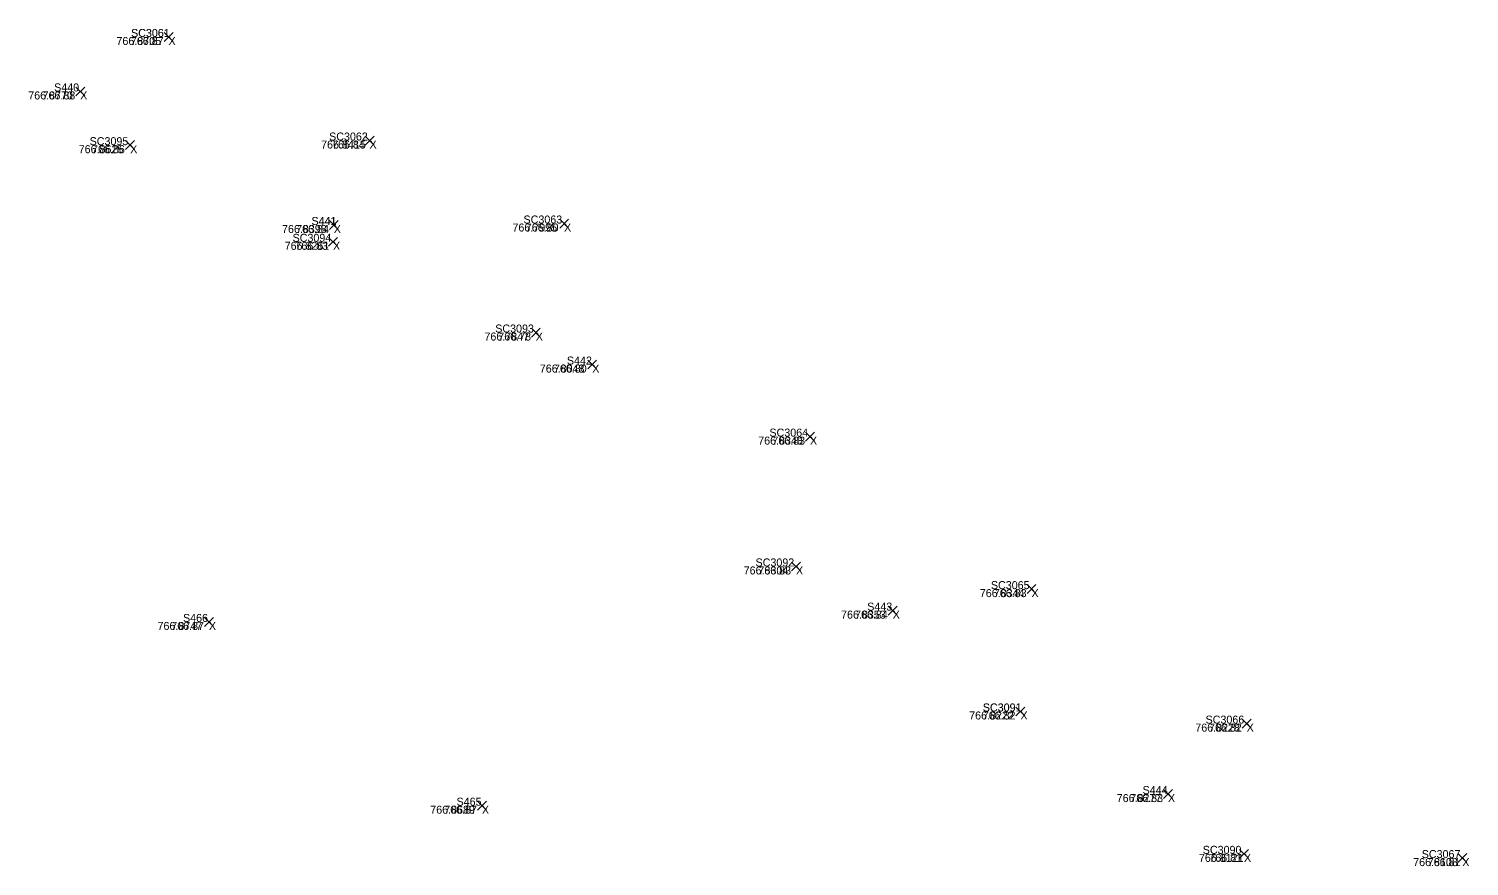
# Model space of a CAD drawing. Extents: x 1845019 to 1877956, y 680444 to 701081.
# Drawn here: x 1857801.14 to 1857811.93, y 694200.78 to 694207.06 of the extents above; entities that cross this region are included whole.
import ezdxf

# ---------------------------------------------------------------- set-up
doc = ezdxf.new("R2010")
doc.units = 0
for name, color, linetype in [('SV_X_Random_Point', 7, 'Continuous'), ('SV_X_Text_Comment', 7, 'Continuous'), ('SV_X_Text_Elevation', 7, 'Continuous'), ('SV_X_Text_Name', 7, 'Continuous')]:
    doc.layers.add(name, color=color, linetype=linetype)

msp = doc.modelspace()

# ---------------------------------------------------------------- linework, layer by layer
at = {"layer": 'SV_X_Random_Point'}
for p, q in [((1857802.152, 694206.966), (1857802.219, 694207.033)), ((1857802.152, 694207.033), (1857802.219, 694206.966)), ((1857802.152, 694206.966), (1857802.219, 694207.033)), ((1857802.152, 694207.033), (1857802.219, 694206.966)), ((1857801.49, 694206.558), (1857801.557, 694206.624)), ((1857801.49, 694206.624), (1857801.557, 694206.558)), ((1857801.49, 694206.558), (1857801.557, 694206.624)), ((1857801.49, 694206.624), (1857801.557, 694206.558)), ((1857801.864, 694206.155), (1857801.931, 694206.222)), ((1857801.864, 694206.222), (1857801.931, 694206.155)), ((1857801.864, 694206.155), (1857801.931, 694206.222)), ((1857801.864, 694206.222), (1857801.931, 694206.155)), ((1857803.659, 694206.189), (1857803.726, 694206.256)), ((1857803.659, 694206.256), (1857803.726, 694206.189)), ((1857803.659, 694206.189), (1857803.726, 694206.256)), ((1857803.659, 694206.256), (1857803.726, 694206.189)), ((1857803.391, 694205.556), (1857803.457, 694205.623)), ((1857803.391, 694205.623), (1857803.457, 694205.556)), ((1857803.391, 694205.556), (1857803.457, 694205.623)), ((1857803.391, 694205.623), (1857803.457, 694205.556)), ((1857805.117, 694205.567), (1857805.183, 694205.634)), ((1857805.117, 694205.634), (1857805.183, 694205.567)), ((1857805.117, 694205.567), (1857805.183, 694205.634)), ((1857805.117, 694205.634), (1857805.183, 694205.567)), ((1857803.385, 694205.431), (1857803.452, 694205.497)), ((1857803.385, 694205.497), (1857803.452, 694205.431)), ((1857803.385, 694205.431), (1857803.452, 694205.497)), ((1857803.385, 694205.497), (1857803.452, 694205.431)), ((1857804.905, 694204.75), (1857804.972, 694204.817)), ((1857804.905, 694204.817), (1857804.972, 694204.75)), ((1857804.905, 694204.75), (1857804.972, 694204.817)), ((1857804.905, 694204.817), (1857804.972, 694204.75)), ((1857805.328, 694204.511), (1857805.394, 694204.578)), ((1857805.328, 694204.578), (1857805.394, 694204.511)), ((1857805.328, 694204.511), (1857805.394, 694204.578)), ((1857805.328, 694204.578), (1857805.394, 694204.511)), ((1857806.959, 694203.971), (1857807.026, 694204.037)), ((1857806.959, 694204.037), (1857807.026, 694203.971)), ((1857806.959, 694203.971), (1857807.026, 694204.037)), ((1857806.959, 694204.037), (1857807.026, 694203.971)), ((1857806.855, 694202.997), (1857806.922, 694203.064)), ((1857806.855, 694203.064), (1857806.922, 694202.997)), ((1857806.855, 694202.997), (1857806.922, 694203.064)), ((1857806.855, 694203.064), (1857806.922, 694202.997)), ((1857808.62, 694202.828), (1857808.686, 694202.895)), ((1857808.62, 694202.895), (1857808.686, 694202.828)), ((1857808.62, 694202.828), (1857808.686, 694202.895)), ((1857808.62, 694202.895), (1857808.686, 694202.828)), ((1857807.579, 694202.666), (1857807.646, 694202.733)), ((1857807.579, 694202.733), (1857807.646, 694202.666)), ((1857807.579, 694202.666), (1857807.646, 694202.733)), ((1857807.579, 694202.733), (1857807.646, 694202.666)), ((1857802.455, 694202.582), (1857802.522, 694202.649)), ((1857802.455, 694202.649), (1857802.522, 694202.582)), ((1857802.455, 694202.582), (1857802.522, 694202.649)), ((1857802.455, 694202.649), (1857802.522, 694202.582)), ((1857808.536, 694201.911), (1857808.603, 694201.977)), ((1857808.536, 694201.977), (1857808.603, 694201.911)), ((1857808.536, 694201.911), (1857808.603, 694201.977)), ((1857808.536, 694201.977), (1857808.603, 694201.911)), ((1857810.232, 694201.82), (1857810.299, 694201.886)), ((1857810.232, 694201.886), (1857810.299, 694201.82)), ((1857810.232, 694201.82), (1857810.299, 694201.886)), ((1857810.232, 694201.886), (1857810.299, 694201.82)), ((1857809.643, 694201.291), (1857809.709, 694201.358)), ((1857809.643, 694201.358), (1857809.709, 694201.291)), ((1857809.643, 694201.291), (1857809.709, 694201.358)), ((1857809.643, 694201.358), (1857809.709, 694201.291)), ((1857804.501, 694201.205), (1857804.568, 694201.272)), ((1857804.501, 694201.272), (1857804.568, 694201.205)), ((1857804.501, 694201.205), (1857804.568, 694201.272)), ((1857804.501, 694201.272), (1857804.568, 694201.205)), ((1857810.212, 694200.844), (1857810.279, 694200.91)), ((1857810.212, 694200.91), (1857810.279, 694200.844)), ((1857810.212, 694200.844), (1857810.279, 694200.91)), ((1857810.212, 694200.91), (1857810.279, 694200.844)), ((1857811.849, 694200.812), (1857811.915, 694200.879)), ((1857811.849, 694200.879), (1857811.915, 694200.812)), ((1857811.849, 694200.812), (1857811.915, 694200.879)), ((1857811.849, 694200.879), (1857811.915, 694200.812))]:
    msp.add_line(p, q, dxfattribs=at)

# ---------------------------------------------------------------- texts
at = {"layer": 'SV_X_Text_Comment'}
for p in [(1857802.185, 694206.939), (1857801.523, 694206.531), (1857801.898, 694206.128), (1857803.692, 694206.163), (1857803.424, 694205.53), (1857805.15, 694205.541), (1857803.418, 694205.404), (1857804.938, 694204.724), (1857805.361, 694204.484), (1857806.993, 694203.944), (1857806.888, 694202.971), (1857808.653, 694202.801), (1857807.613, 694202.64), (1857802.488, 694202.555), (1857808.57, 694201.884), (1857810.266, 694201.793), (1857809.676, 694201.265), (1857804.534, 694201.178), (1857810.246, 694200.817), (1857811.882, 694200.785)]:
    msp.add_text('X', height=0.06, dxfattribs=at).set_placement(p)
at = {"layer": 'SV_X_Text_Elevation'}
for s, p in [('766.8705', (1857801.795, 694206.939)), ('766.87', (1857801.903, 694206.939)), ('766.8770', (1857801.134, 694206.531)), ('766.88', (1857801.241, 694206.531)), ('766.8625', (1857801.512, 694206.128)), ('766.86', (1857801.612, 694206.128)), ('766.8415', (1857803.329, 694206.163)), ('766.84', (1857803.411, 694206.163)), ('766.8398', (1857803.036, 694205.53)), ('766.84', (1857803.142, 694205.53)), ('766.7995', (1857804.763, 694205.541)), ('766.80', (1857804.863, 694205.541)), ('766.8261', (1857803.056, 694205.404)), ('766.83', (1857803.136, 694205.404)), ('766.7847', (1857804.553, 694204.724)), ('766.78', (1857804.657, 694204.724)), ('766.8048', (1857804.968, 694204.484)), ('766.80', (1857805.074, 694204.484)), ('766.8348', (1857806.605, 694203.944)), ('766.83', (1857806.711, 694203.944)), ('766.8304', (1857806.496, 694202.971)), ('766.83', (1857806.606, 694202.971)), ('766.8344', (1857808.266, 694202.801)), ('766.83', (1857808.371, 694202.801)), ('766.8353', (1857807.226, 694202.64)), ('766.84', (1857807.331, 694202.64)), ('766.8747', (1857802.103, 694202.555)), ('766.87', (1857802.206, 694202.555)), ('766.8222', (1857808.186, 694201.884)), ('766.82', (1857808.288, 694201.884)), ('766.8228', (1857809.881, 694201.793)), ('766.82', (1857809.984, 694201.793)), ('766.8277', (1857809.292, 694201.265)), ('766.83', (1857809.394, 694201.265)), ('766.8689', (1857804.147, 694201.178)), ('766.87', (1857804.252, 694201.178)), ('766.8121', (1857809.908, 694200.817)), ('766.81', (1857809.986, 694200.817)), ('766.8108', (1857811.514, 694200.785)), ('766.81', (1857811.623, 694200.785))]:
    msp.add_text(s, height=0.06, dxfattribs=at).set_placement(p)
at = {"layer": 'SV_X_Text_Name'}
for s, p in [('SC3061', (1857801.904, 694206.999)), ('SC3061', (1857801.905, 694206.999)), ('S440', (1857801.328, 694206.591)), ('S440', (1857801.328, 694206.591)), ('SC3062', (1857803.389, 694206.223)), ('SC3062', (1857803.389, 694206.223)), ('SC3095', (1857801.594, 694206.188)), ('SC3095', (1857801.594, 694206.188)), ('S441', (1857803.256, 694205.59)), ('S441', (1857803.257, 694205.59)), ('SC3063', (1857804.846, 694205.601)), ('SC3063', (1857804.846, 694205.601)), ('SC3094', (1857803.115, 694205.464)), ('SC3094', (1857803.115, 694205.464)), ('SC3093', (1857804.634, 694204.784)), ('SC3093', (1857804.634, 694204.784)), ('S442', (1857805.171, 694204.544)), ('S442', (1857805.171, 694204.544)), ('SC3064', (1857806.689, 694204.004)), ('SC3064', (1857806.689, 694204.004)), ('SC3092', (1857806.585, 694203.031)), ('SC3092', (1857806.585, 694203.031)), ('SC3065', (1857808.349, 694202.861)), ('SC3065', (1857808.349, 694202.861)), ('S443', (1857807.422, 694202.7)), ('S443', (1857807.422, 694202.7)), ('S466', (1857802.294, 694202.615)), ('S466', (1857802.294, 694202.615)), ('SC3091', (1857808.288, 694201.944)), ('SC3091', (1857808.289, 694201.944)), ('SC3066', (1857809.958, 694201.853)), ('SC3066', (1857809.958, 694201.853)), ('S465', (1857804.344, 694201.238)), ('S465', (1857804.344, 694201.238)), ('S444', (1857809.486, 694201.325)), ('S444', (1857809.486, 694201.325)), ('SC3090', (1857809.937, 694200.877)), ('SC3090', (1857809.937, 694200.877)), ('SC3067', (1857811.578, 694200.845)), ('SC3067', (1857811.578, 694200.845))]:
    msp.add_text(s, height=0.06, dxfattribs=at).set_placement(p)

doc.saveas('drawing.dxf')
